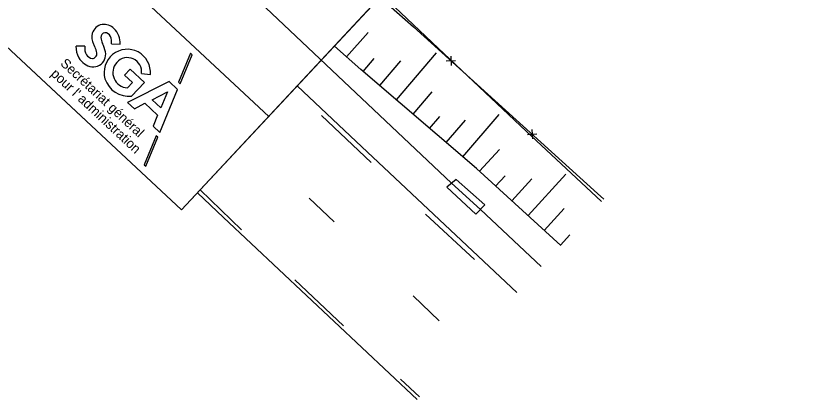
# Model space of a CAD drawing. Extents: x 343997 to 344255, y 298512 to 298767.
# Drawn here: x 344139.61 to 344175.3, y 298512.16 to 298529.67 of the extents above; entities that cross this region are included whole.
import ezdxf

# ---------------------------------------------------------------- set-up
doc = ezdxf.new("R2010")
doc.units = 0
for name, color, linetype in [('DH_CADRE -CARTOUCHE', 7, 'Continuous'), ('IMM_VOIRIE VOIE FERREE', 7, 'Continuous'), ('LIB_01', 7, 'Continuous'), ('PS_HIDDEN', 7, 'Continuous'), ('PS_OBJECT', 7, 'Continuous'), ('PS_WELD', 7, 'Continuous'), ('RES_TELEPHONE SOUTERRAIN', 7, 'Continuous')]:
    doc.layers.add(name, color=color, linetype=linetype)

msp = doc.modelspace()

# ---------------------------------------------------------------- linework, layer by layer
at = {"layer": 'DH_CADRE -CARTOUCHE'}
for p, q in [((344124.053, 298550.372), (344151.163, 298525.072)), ((344142.761, 298528.274), (344142.362, 298528.276)), ((344143.977, 298528.377), (344144.376, 298528.37)), ((344147.595, 298527.954), (344147.041, 298526.631)), ((344147.112, 298526.565), (344147.666, 298527.888)), ((344147.666, 298527.888), (344147.595, 298527.954)), ((344145.354, 298527.024), (344145.757, 298526.983)), ((344147.041, 298526.631), (344147.112, 298526.565)), ((344146.027, 298524.188), (344145.473, 298522.865)), ((344145.544, 298522.798), (344146.098, 298524.121)), ((344146.098, 298524.121), (344146.027, 298524.188)), ((344145.473, 298522.865), (344145.544, 298522.798))]:
    msp.add_line(p, q, dxfattribs=at)
for points in [[(343997.309, 298660.673), (344147.183, 298520.807), (344245.09, 298625.72), (344095.215, 298765.586)], [(344086.014, 298601.829), (344159.123, 298533.601), (344147.183, 298520.807), (344074.074, 298589.035)], [(344146.189, 298524.339), (344147.001, 298526.299), (344146.615, 298526.658), (344144.717, 298525.713), (344145.027, 298525.424), (344145.511, 298525.669), (344146.09, 298525.129), (344145.879, 298524.629)], [(344146.538, 298526.189), (344146.233, 298525.467), (344145.838, 298525.835)]]:
    msp.add_lwpolyline(points, close=True, dxfattribs=at)
msp.add_lwpolyline([(344144.902, 298525.992), (344145.487, 298526.619), (344144.831, 298527.231), (344144.578, 298526.96), (344144.94, 298526.623), (344144.71, 298526.377)], dxfattribs=at)
for centre, radius, start, end in [((344143.663, 298528.693), 0.584, 101.1772, 162.9378), ((344143.642, 298528.648), 0.624, 42.9888, 98.5465), ((344143.508, 298528.434), 0.871, 355.7773, 47.2891), ((344143.826, 298528.702), 0.74, 167.3792, 206.6711), ((344143.698, 298528.69), 0.201, 96.5362, 185.099), ((344144.054, 298528.688), 0.557, 181.6137, 210.3509), ((344143.691, 298528.635), 0.255, 19.0043, 93.6383), ((344143.326, 298528.466), 0.657, 352.1595, 22.583), ((344143.322, 298528.225), 0.962, 176.9623, 209.5034), ((344143.415, 298528.2), 0.658, 173.5604, 208.8754), ((344144.697, 298528.99), 1.653, 202.0297, 207.4887), ((344142.438, 298527.841), 0.882, 8.5308, 25.9665), ((344141.058, 298527.325), 2.738, 14.5723, 23.257), ((344143.148, 298528.083), 0.369, 213.102, 264.2531), ((344143.11, 298527.928), 0.205, 315.6878, 12.2616), ((344143.152, 298527.902), 0.567, 299.9891, 11.4061), ((344144.702, 298527.076), 1.059, 354.9784, 196.1622), ((344143.493, 298528.437), 1.218, 214.2577, 231.9855), ((344143.137, 298527.942), 0.609, 229.6707, 299.3798), ((344143.117, 298527.892), 0.176, 267.8657, 322.5447), ((344144.736, 298527.068), 0.692, 138.0867, 267.8662), ((344144.71, 298527.106), 0.649, 352.7061, 139.0633), ((344144.79, 298527.152), 1.166, 198.5624, 275.4776)]:
    msp.add_arc(centre, radius, start, end, dxfattribs=at)
at = {"layer": 'IMM_VOIRIE VOIE FERREE'}
for p, q in [((344148.029, 298521.713), (344149.917, 298519.898)), ((344157.182, 298513.083), (344158.043, 298512.272))]:
    msp.add_line(p, q, dxfattribs=at)
for points in [[(344162.482, 298517.029), (344155.153, 298523.931), (344152.466, 298526.468)], [(344155.833, 298522.971), (344153.578, 298525.107)], [(344157.934, 298512.155), (344149.102, 298520.459), (344147.904, 298521.58)], [(344154.142, 298520.26), (344153.002, 298521.342)], [(344160.554, 298518.534), (344158.323, 298520.614)], [(344152.354, 298517.612), (344154.568, 298515.517)], [(344158.942, 298515.745), (344157.763, 298516.88)]]:
    msp.add_lwpolyline(points, dxfattribs=at)
at = {"layer": 'LIB_01'}
msp.add_lwpolyline([(344159.287, 298521.843), (344160.623, 298520.612), (344161.025, 298521.029), (344159.721, 298522.195), (344159.287, 298521.843)], dxfattribs=at)
at = {"layer": 'PS_HIDDEN'}
msp.add_arc((344140.897, 298525.565), 1, 0, 0, dxfattribs=at)
at = {"layer": 'PS_OBJECT'}
for p, q in [((344154.719, 298527.788), (344155.7, 298528.901)), ((344156.99, 298525.826), (344158.828, 298527.971)), ((344155.471, 298527.128), (344155.98, 298527.722)), ((344156.23, 298526.477), (344157.198, 298527.606)), ((344157.749, 298525.175), (344158.622, 298526.194)), ((344158.509, 298524.524), (344158.969, 298525.062)), ((344160.028, 298523.223), (344161.689, 298525.161)), ((344159.268, 298523.873), (344160.143, 298524.894)), ((344160.783, 298522.567), (344161.691, 298523.562)), ((344161.522, 298521.893), (344161.953, 298522.365)), ((344162.261, 298521.218), (344163.171, 298522.215)), ((344162.999, 298520.544), (344164.728, 298522.437)), ((344163.738, 298519.869), (344164.65, 298520.868)), ((344164.477, 298519.195), (344164.91, 298519.669))]:
    msp.add_line(p, q, dxfattribs=at)
for points in [[(344156.345, 298530.624), (344158.9, 298528.182), (344162.908, 298524.399), (344166.357, 298521.182)], [(344164.491, 298519.182), (344160.645, 298522.694), (344155.373, 298527.211), (344154.159, 298528.282)]]:
    msp.add_lwpolyline(points, dxfattribs=at)
at = {"layer": 'PS_WELD'}
for p, q in [((344159.47, 298527.826), (344159.492, 298527.402)), ((344159.269, 298527.604), (344159.693, 298527.625)), ((344162.978, 298524.25), (344163.402, 298524.272)), ((344163.179, 298524.473), (344163.201, 298524.049))]:
    msp.add_line(p, q, dxfattribs=at)
msp.add_lwpolyline([(344156.249, 298530.521), (344157.765, 298529.166), (344166.179, 298521.559), (344166.464, 298521.295)], dxfattribs=at)
at = {"layer": 'RES_TELEPHONE SOUTERRAIN'}
msp.add_lwpolyline([(344006.37, 298666.609), (344159.504, 298522.019), (344160.824, 298520.82), (344163.6, 298518.226)], dxfattribs=at)

# ---------------------------------------------------------------- texts
at = {"layer": 'DH_CADRE -CARTOUCHE'}
for s, height, p in [('Secrétariat général', 0.43611, (344141.62, 298527.447)), ("pour l'", 0.4361, (344141.182, 298526.973)), ('administration', 0.43611, (344142.417, 298525.819))]:
    msp.add_text(s, height=height, rotation=316.9784, dxfattribs=at).set_placement(p)

doc.saveas('drawing.dxf')
